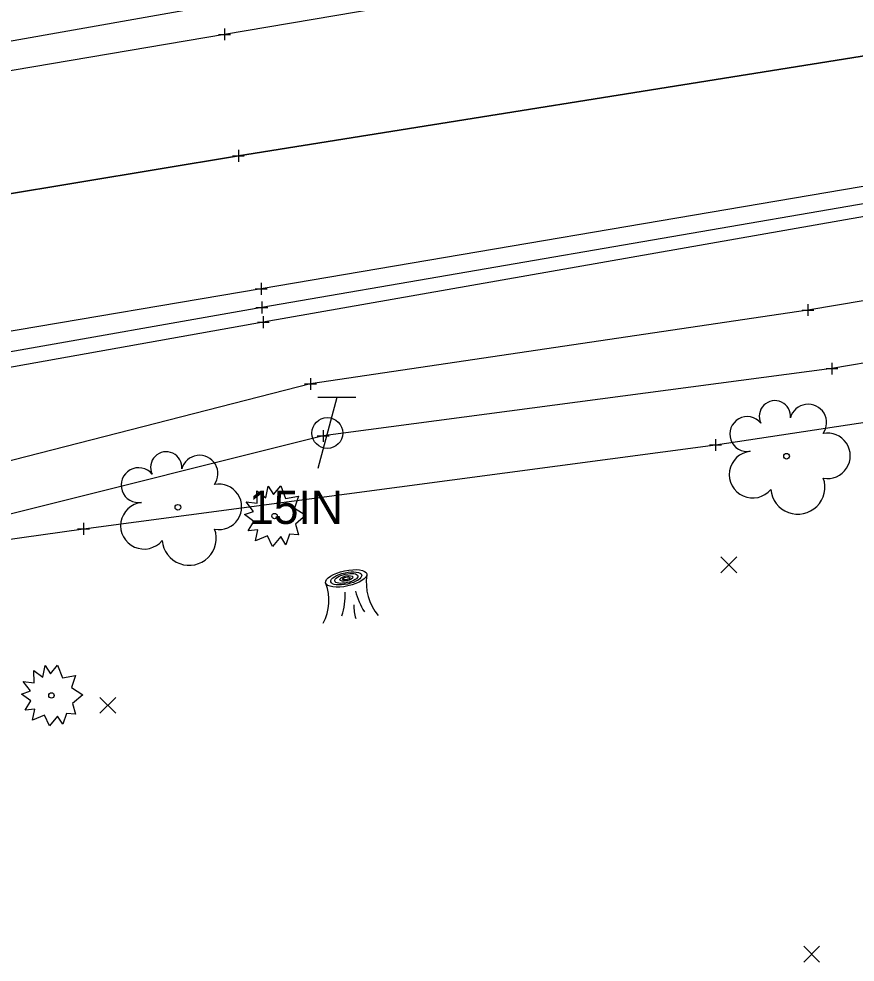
# Model space of a CAD drawing. Extents: x 1386013 to 1389776, y 604170 to 607009.
# Drawn here: x 1387157 to 1387227.5, y 604701.9 to 604781.5 of the extents above; entities that cross this region are included whole.
import ezdxf

# ---------------------------------------------------------------- set-up
doc = ezdxf.new("R2010")
doc.units = 0
for name, color, linetype in [('_CIVIL_CONSTRUCTION', 7, 'Continuous'), ('DV_X_Text', 7, 'Continuous'), ('PM_X_CL_Double_Solid', 7, 'Continuous'), ('PV_X_COP', 7, 'Continuous'), ('PV_X_EOP', 7, 'Continuous'), ('PV_X_Shoulder', 7, 'Continuous'), ('SV_X_Random_Point', 7, 'Continuous'), ('SV_X_Toe_of_Slope', 7, 'Continuous'), ('SV_X_Top_of_Bank', 7, 'Continuous'), ('UT_X_Telecom_Cells', 7, 'Continuous'), ('VG_X_Text', 7, 'Continuous')]:
    doc.layers.add(name, color=color, linetype=linetype)

msp = doc.modelspace()

# ---------------------------------------------------------------- linework, layer by layer
at = {"layer": '_CIVIL_CONSTRUCTION'}
msp.add_line((1387184.983, 604732.773), (1387184.983, 604732.773), dxfattribs=at)
for points in [[(1387178.477, 604741.347), (1387179.082, 604742.082), (1387179.497, 604741.029), (1387180.589, 604741.209), (1387180.25, 604740.197), (1387181.195, 604739.602), (1387180.339, 604738.867), (1387180.589, 604737.954), (1387179.835, 604738.022), (1387179.51, 604737.109), (1387179.082, 604737.801), (1387178.404, 604736.984), (1387177.975, 604737.871), (1387176.955, 604737.441), (1387177.147, 604738.382), (1387176.335, 604738.299), (1387176.809, 604739.089), (1387176.04, 604739.657), (1387176.779, 604739.921), (1387176.172, 604740.724), (1387177.104, 604740.614), (1387177.074, 604741.652), (1387177.827, 604741.084), (1387178.034, 604742.069), (1387178.477, 604741.347)], [(1387159.676, 604726.224), (1387160.281, 604726.959), (1387160.696, 604725.906), (1387161.788, 604726.086), (1387161.449, 604725.074), (1387162.394, 604724.479), (1387161.538, 604723.744), (1387161.788, 604722.831), (1387161.034, 604722.899), (1387160.709, 604721.986), (1387160.281, 604722.678), (1387159.603, 604721.861), (1387159.174, 604722.748), (1387158.154, 604722.318), (1387158.346, 604723.259), (1387157.534, 604723.176), (1387158.008, 604723.966), (1387157.239, 604724.534), (1387157.978, 604724.798), (1387157.371, 604725.601), (1387158.303, 604725.491), (1387158.273, 604726.529), (1387159.026, 604725.961), (1387159.233, 604726.946), (1387159.676, 604726.224)]]:
    msp.add_lwpolyline(points, dxfattribs=at)
for centre, radius in [((1387221.723, 604744.583), 0.24), ((1387170.416, 604740.277), 0.24), ((1387178.561, 604739.538), 0.23), ((1387159.76, 604724.415), 0.23)]:
    msp.add_circle(centre, radius, dxfattribs=at)
for centre, radius, start, end in [((1387220.739, 604747.95), 1.317, 354.0047, 205.97412), ((1387223.549, 604747.412), 1.553, 323.82996, 165.0376), ((1387218.414, 604746.447), 1.471, 39.06254, 279.54124), ((1387225.183, 604744.619), 1.915, 259.14531, 101.45961), ((1387169.432, 604743.644), 1.317, 354.0047, 205.97412), ((1387172.242, 604743.106), 1.553, 323.82996, 165.0376), ((1387218.87, 604743.034), 1.974, 96.17219, 320.57371), ((1387167.107, 604742.141), 1.471, 39.06254, 279.54124), ((1387173.876, 604740.313), 1.915, 259.14531, 101.45961), ((1387222.669, 604741.978), 2.284, 184.94757, 19.45715), ((1387167.563, 604738.728), 1.974, 96.17219, 320.57371), ((1387171.362, 604737.672), 2.284, 184.94757, 19.45715), ((1387190.588, 604733.913), 4.292, 171.41061, 219.91939), ((1387179.151, 604732.426), 4.003, 331.53375, 20.92689), ((1387179.466, 604732.798), 5.053, 340.79377, 3.54808), ((1387191.491, 604734.829), 6.319, 194.9653, 212.12159), ((1387188.888, 604731.972), 3.639, 178.79264, 197.12241)]:
    msp.add_arc(centre, radius, start, end, dxfattribs=at)
for major_axis in [(1.736, 0.375), (1.302, 0.281), (0.976, 0.211), (0.549, 0.119), (0.309, 0.067)]:
    msp.add_ellipse((1387184.608, 604734.283), major_axis=major_axis, ratio=0.36865, dxfattribs=at)
at = {"layer": 'DV_X_Text'}
for p, q in [((1387174.346, 604780.647), (1387174.346, 604779.647)), ((1387173.846, 604780.147), (1387174.846, 604780.147)), ((1387174.346, 604780.147), (1387174.346, 604780.147)), ((1387175.516, 604770.399), (1387175.516, 604769.399)), ((1387175.016, 604769.899), (1387176.016, 604769.899)), ((1387175.516, 604769.899), (1387175.516, 604769.899)), ((1387177.431, 604759.197), (1387177.431, 604758.197)), ((1387176.931, 604758.697), (1387177.931, 604758.697)), ((1387177.431, 604758.697), (1387177.431, 604758.697)), ((1387177.496, 604757.627), (1387177.496, 604756.627)), ((1387223.528, 604757.41), (1387223.528, 604756.41)), ((1387176.996, 604757.127), (1387177.996, 604757.127)), ((1387177.496, 604757.127), (1387177.496, 604757.127)), ((1387223.028, 604756.91), (1387224.028, 604756.91)), ((1387223.528, 604756.91), (1387223.528, 604756.91)), ((1387177.115, 604755.882), (1387178.115, 604755.882)), ((1387177.615, 604756.382), (1387177.615, 604755.382)), ((1387177.615, 604755.882), (1387177.615, 604755.882)), ((1387225.55, 604752.465), (1387225.55, 604751.465)), ((1387225.05, 604751.965), (1387226.05, 604751.965)), ((1387225.55, 604751.965), (1387225.55, 604751.965)), ((1387181.6, 604751.173), (1387181.6, 604750.173)), ((1387181.1, 604750.673), (1387182.1, 604750.673)), ((1387181.6, 604750.673), (1387181.6, 604750.673)), ((1387182.161, 604746.288), (1387183.161, 604746.288)), ((1387182.661, 604746.788), (1387182.661, 604745.788)), ((1387182.661, 604746.288), (1387182.661, 604746.288)), ((1387215.238, 604745.531), (1387216.238, 604745.531)), ((1387215.738, 604746.031), (1387215.738, 604745.031)), ((1387215.738, 604745.531), (1387215.738, 604745.531)), ((1387162.467, 604738.959), (1387162.467, 604737.959)), ((1387161.967, 604738.459), (1387162.967, 604738.459)), ((1387162.467, 604738.459), (1387162.467, 604738.459))]:
    msp.add_line(p, q, dxfattribs=at)
at = {"layer": 'PM_X_CL_Double_Solid'}
msp.add_lwpolyline([(1386941.923, 604730.568), (1387000.365, 604739.899), (1387059.378, 604750.405), (1387127.324, 604761.935), (1387175.516, 604769.899), (1387233.308, 604779.132), (1387291.846, 604789.882), (1387343.041, 604798.389), (1387403.896, 604809.054), (1387458.493, 604818.933), (1387516.124, 604829.584), (1387574.819, 604839.732), (1387636.991, 604851.11), (1387704.346, 604863.012), (1387787.502, 604877.74), (1387859.733, 604890.761), (1387934.468, 604903.864), (1387998.852, 604914.969), (1388072.268, 604927.437)], dxfattribs=at)
at = {"layer": 'PV_X_COP'}
msp.add_lwpolyline([(1388072.268, 604927.437), (1387998.852, 604914.969), (1387934.468, 604903.864), (1387859.733, 604890.761), (1387787.502, 604877.74), (1387704.346, 604863.012), (1387636.991, 604851.11), (1387574.819, 604839.732), (1387516.124, 604829.584), (1387458.493, 604818.933), (1387403.896, 604809.054), (1387343.041, 604798.389), (1387291.846, 604789.882), (1387233.308, 604779.132), (1387175.516, 604769.899), (1387127.324, 604761.935), (1387059.378, 604750.405), (1387000.365, 604739.899), (1386941.923, 604730.568)], dxfattribs=at)
at = {"layer": 'PV_X_EOP'}
for points in [[(1388070.904, 604937.92), (1387997.667, 604925.455), (1387932.448, 604914.147), (1387857.846, 604900.917), (1387785.098, 604888.089), (1387704.04, 604873.647), (1387634.939, 604861.367), (1387573.227, 604850.33), (1387514.484, 604840.103), (1387457.169, 604829.653), (1387402.439, 604819.904), (1387341.383, 604808.9), (1387290.361, 604800.04), (1387231.983, 604789.906), (1387174.346, 604780.147), (1387125.76, 604771.911), (1387057.817, 604760.304), (1386999.091, 604750.972), (1386941.405, 604741.044)], [(1388073.477, 604916.736), (1388000.199, 604904.184), (1387936.608, 604893.172), (1387860.997, 604879.892), (1387788.154, 604866.907), (1387706.182, 604852.378), (1387637.623, 604840.161), (1387577.036, 604829.262), (1387518.08, 604818.578), (1387459.961, 604808.241), (1387405.362, 604798.504), (1387345.113, 604787.749), (1387291.8, 604778.426), (1387234.86, 604768.47), (1387177.431, 604758.697), (1387129.398, 604750.563), (1387061.715, 604739.203), (1387002.895, 604729.166), (1386943.417, 604719.405)]]:
    msp.add_lwpolyline(points, dxfattribs=at)
at = {"layer": 'PV_X_Shoulder'}
for points in [[(1388070.878, 604939.746), (1387997.08, 604927.243), (1387932.098, 604916.229), (1387857.343, 604902.988), (1387785.161, 604890.04), (1387703.388, 604875.425), (1387634.349, 604863.658), (1387572.417, 604852.644), (1387514.095, 604842.112), (1387456.78, 604832.264), (1387401.906, 604822.43), (1387340.627, 604811.343), (1387290.105, 604802.669), (1387231.448, 604791.93), (1387174.182, 604782.714), (1387125.331, 604774.104), (1387057.538, 604762.256), (1386998.586, 604752.703), (1386940.974, 604743.321)], [(1388073.661, 604915.378), (1388000.633, 604902.689), (1387936.793, 604891.841), (1387860.981, 604878.417), (1387788.185, 604865.058), (1387706.381, 604850.403), (1387637.881, 604838.495), (1387577.023, 604827.533), (1387518.116, 604817.165), (1387460.261, 604806.851), (1387405.505, 604796.968), (1387345.324, 604786.502), (1387292.135, 604776.932), (1387235.042, 604767.03), (1387177.496, 604757.127), (1387129.278, 604748.594), (1387117.652, 604744.892), (1387099.288, 604741.913), (1387094.703, 604743.054), (1387062.03, 604737.865), (1387002.752, 604727.469), (1386990.609, 604725.246), (1386985.404, 604722.838), (1386965.111, 604719.464)]]:
    msp.add_lwpolyline(points, dxfattribs=at)
at = {"layer": 'SV_X_Random_Point'}
for p, q in [((1387216.19, 604734.765), (1387217.524, 604736.1)), ((1387216.19, 604736.1), (1387217.524, 604734.765)), ((1387163.84, 604722.918), (1387165.174, 604724.253)), ((1387163.84, 604724.253), (1387165.174, 604722.918)), ((1387223.179, 604701.932), (1387224.513, 604703.267)), ((1387223.179, 604703.267), (1387224.513, 604701.932))]:
    msp.add_line(p, q, dxfattribs=at)
at = {"layer": 'SV_X_Toe_of_Slope'}
for points in [[(1387642.644, 604832.214), (1387598.475, 604823.295), (1387558.951, 604817.367), (1387510.991, 604808.944), (1387471.623, 604802.749), (1387417.674, 604793.627), (1387365.328, 604784.072), (1387322.852, 604775.638), (1387270.329, 604764.795), (1387223.528, 604756.91), (1387181.6, 604750.673), (1387155.521, 604743.997), (1387129.15, 604740.805), (1387125.031, 604741.781), (1387120.426, 604741.023)], [(1387645.487, 604830.059), (1387640.632, 604828.806), (1387599.431, 604819.649), (1387560.444, 604813.109), (1387511.639, 604804.792), (1387472.902, 604799.006), (1387418.895, 604788.909), (1387366.412, 604779.888), (1387324.468, 604770.631), (1387271.89, 604759.841), (1387225.55, 604751.965), (1387182.661, 604746.288), (1387156.282, 604739.691), (1387120.849, 604736.529)]]:
    msp.add_lwpolyline(points, dxfattribs=at)
at = {"layer": 'SV_X_Top_of_Bank'}
for points in [[(1387579.309, 604826.78), (1387518.181, 604816.157), (1387495.205, 604811.897), (1387460.53, 604806.404), (1387405.654, 604795.747), (1387345.732, 604785.646), (1387292.402, 604775.678), (1387235, 604765.96), (1387177.615, 604755.882), (1387129.658, 604747.304), (1387125.36, 604745.567), (1387119.562, 604742.591), (1387120.12, 604734.169)], [(1387120.443, 604732.558), (1387162.467, 604738.459), (1387215.738, 604745.531), (1387273.799, 604754.329), (1387315.903, 604762.485), (1387378.293, 604774.446), (1387445.093, 604787.578), (1387492.001, 604798.409), (1387538.689, 604807.909), (1387587.499, 604815.895), (1387625.324, 604823.628), (1387642.483, 604825.613)]]:
    msp.add_lwpolyline(points, dxfattribs=at)
at = {"layer": 'UT_X_Telecom_Cells'}
for p, q in [((1387183.814, 604749.535), (1387182.208, 604743.535)), ((1387185.414, 604749.535), (1387182.214, 604749.535))]:
    msp.add_line(p, q, dxfattribs=at)
msp.add_circle((1387183.011, 604746.535), 1.3, dxfattribs=at)

# ---------------------------------------------------------------- texts
at = {"layer": 'VG_X_Text'}
msp.add_text('15IN', height=2.8, dxfattribs=at).set_placement((1387176.416, 604738.877))

doc.saveas('drawing.dxf')
